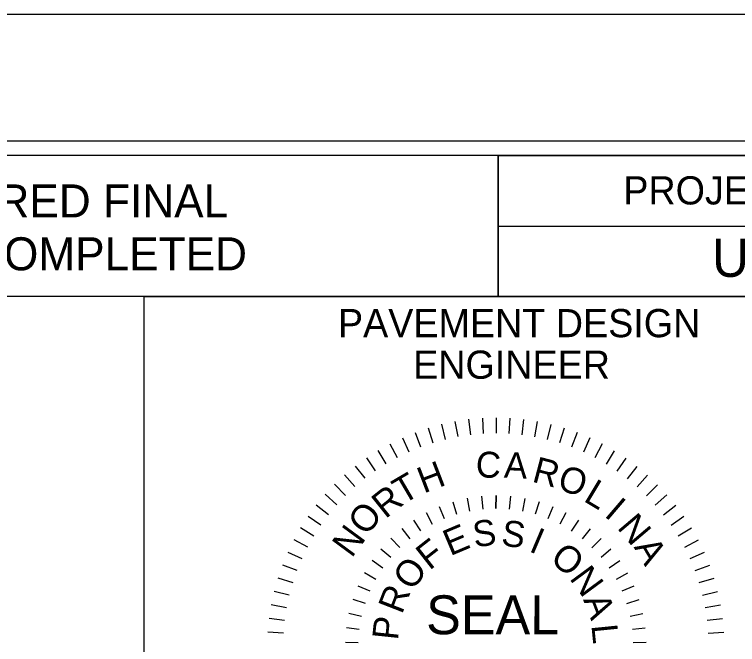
# Model space of a CAD drawing. Extents: x 2294370 to 2294957, y 719276 to 719941.
# Drawn here: x 2294731.39 to 2294757.04, y 719473.99 to 719496.34 of the extents above; entities that cross this region are included whole.
import ezdxf

# ---------------------------------------------------------------- set-up
doc = ezdxf.new("R2010")
doc.units = 0
for name, color, linetype in [('Default', 7, 'Continuous'), ('Sheet Cutting Line CELL', 7, 'Continuous'), ('Sheet Data Field CELL', 7, 'Continuous'), ('Sheet Plan CELL', 7, 'Continuous'), ('Sheet Plot Border Inside CELL', 7, 'Continuous'), ('Sheet Plot Border Outside CELL', 7, 'Continuous'), ('Sheet Sticker Exception Certification CELL', 7, 'Continuous'), ('Sheet Typical CELL', 7, 'Continuous')]:
    doc.layers.add(name, color=color, linetype=linetype)

msp = doc.modelspace()

# ---------------------------------------------------------------- linework, layer by layer
at = {"layer": 'Default'}
for p, q in [((2294747.502, 719481.976), (2294747.568, 719481.428)), ((2294747.99, 719482.019), (2294748.022, 719481.468)), ((2294748.479, 719482.033), (2294748.478, 719481.481)), ((2294748.968, 719482.018), (2294748.934, 719481.467)), ((2294749.455, 719481.973), (2294749.388, 719481.425)), ((2294746.541, 719481.801), (2294746.671, 719481.265)), ((2294747.019, 719481.903), (2294747.117, 719481.36)), ((2294749.939, 719481.899), (2294749.839, 719481.356)), ((2294750.417, 719481.796), (2294750.285, 719481.26)), ((2294745.606, 719481.512), (2294745.801, 719480.995)), ((2294746.068, 719481.671), (2294746.232, 719481.142)), ((2294750.889, 719481.664), (2294750.724, 719481.136)), ((2294751.35, 719481.504), (2294751.154, 719480.987)), ((2294745.154, 719481.324), (2294745.379, 719480.821)), ((2294751.802, 719481.315), (2294751.575, 719480.812)), ((2294744.713, 719481.111), (2294744.969, 719480.622)), ((2294752.242, 719481.101), (2294751.985, 719480.612)), ((2294744.286, 719480.871), (2294744.572, 719480.399)), ((2294752.668, 719480.859), (2294752.381, 719480.388)), ((2294743.875, 719480.606), (2294744.188, 719480.152)), ((2294753.078, 719480.593), (2294752.764, 719480.14)), ((2294743.481, 719480.317), (2294743.821, 719479.882)), ((2294753.472, 719480.303), (2294753.131, 719479.869)), ((2294743.105, 719480.004), (2294743.47, 719479.59)), ((2294753.848, 719479.989), (2294753.481, 719479.576)), ((2294742.748, 719479.669), (2294743.138, 719479.278)), ((2294754.203, 719479.653), (2294753.812, 719479.263)), ((2294742.412, 719479.314), (2294742.825, 719478.947)), ((2294747.449, 719479.174), (2294747.537, 719478.722)), ((2294747.959, 719479.248), (2294748.003, 719478.79)), ((2294748.475, 719479.272), (2294748.474, 719478.812)), ((2294748.474, 719478.812), (2294748.475, 719479.272)), ((2294748.991, 719479.246), (2294748.945, 719478.789)), ((2294749.5, 719479.171), (2294749.412, 719478.72)), ((2294754.538, 719479.296), (2294754.124, 719478.931)), ((2294742.098, 719478.938), (2294742.532, 719478.597)), ((2294746.948, 719479.052), (2294747.079, 719478.61)), ((2294750.001, 719479.047), (2294749.869, 719478.606)), ((2294754.851, 719478.92), (2294754.416, 719478.58)), ((2294745.993, 719478.664), (2294746.206, 719478.257)), ((2294746.461, 719478.881), (2294746.634, 719478.454)), ((2294750.488, 719478.876), (2294750.314, 719478.449)), ((2294750.955, 719478.657), (2294750.741, 719478.25)), ((2294741.808, 719478.544), (2294742.261, 719478.23)), ((2294745.548, 719478.403), (2294745.799, 719478.017)), ((2294751.4, 719478.395), (2294751.147, 719478.01)), ((2294755.14, 719478.526), (2294754.686, 719478.213)), ((2294741.542, 719478.134), (2294742.013, 719477.847)), ((2294755.405, 719478.115), (2294754.933, 719477.829)), ((2294745.13, 719478.101), (2294745.418, 719477.741)), ((2294751.817, 719478.091), (2294751.528, 719477.732)), ((2294741.3, 719477.708), (2294741.789, 719477.451)), ((2294744.744, 719477.759), (2294745.065, 719477.429)), ((2294752.202, 719477.748), (2294751.88, 719477.419)), ((2294755.645, 719477.688), (2294755.156, 719477.432)), ((2294744.392, 719477.382), (2294744.743, 719477.085)), ((2294752.553, 719477.37), (2294752.201, 719477.074)), ((2294741.086, 719477.268), (2294741.589, 719477.041)), ((2294755.858, 719477.247), (2294755.355, 719477.022)), ((2294744.078, 719476.973), (2294744.456, 719476.71)), ((2294752.866, 719476.96), (2294752.487, 719476.699)), ((2294740.897, 719476.817), (2294741.414, 719476.62)), ((2294756.046, 719476.795), (2294755.529, 719476.6)), ((2294740.737, 719476.355), (2294741.265, 719476.19)), ((2294743.806, 719476.535), (2294744.207, 719476.31)), ((2294753.137, 719476.522), (2294752.735, 719476.298)), ((2294756.205, 719476.333), (2294755.676, 719476.169)), ((2294743.576, 719476.072), (2294743.998, 719475.888)), ((2294740.605, 719475.883), (2294741.141, 719475.751)), ((2294753.365, 719476.058), (2294752.943, 719475.875)), ((2294756.335, 719475.86), (2294755.799, 719475.73)), ((2294743.393, 719475.59), (2294743.831, 719475.448)), ((2294753.547, 719475.576), (2294753.109, 719475.435)), ((2294740.502, 719475.405), (2294741.045, 719475.305)), ((2294756.437, 719475.382), (2294755.894, 719475.284)), ((2294743.256, 719475.093), (2294743.705, 719474.993)), ((2294753.682, 719475.078), (2294753.232, 719474.98)), ((2294740.428, 719474.921), (2294740.976, 719474.854)), ((2294756.51, 719474.899), (2294755.962, 719474.833)), ((2294743.169, 719474.584), (2294743.625, 719474.529)), ((2294753.768, 719474.569), (2294753.312, 719474.515)), ((2294740.383, 719474.434), (2294740.934, 719474.4)), ((2294756.553, 719474.411), (2294756.002, 719474.379)), ((2294743.13, 719474.07), (2294743.59, 719474.058)), ((2294753.805, 719474.055), (2294753.345, 719474.044))]:
    msp.add_line(p, q, dxfattribs=at)
at = {"layer": 'Sheet Cutting Line CELL'}
msp.add_line((2294791.96, 719496.338), (2294455.16, 719496.338), dxfattribs=at)
at = {"layer": 'Sheet Plan CELL'}
msp.add_lwpolyline([(2294762.275, 719463.828), (2294735.99, 719463.828), (2294735.99, 719486.328), (2294762.275, 719486.328)], dxfattribs=at)
at = {"layer": 'Sheet Plot Border Inside CELL'}
msp.add_lwpolyline([(2294791.06, 719491.848), (2294457.76, 719491.848), (2294457.76, 719280.828), (2294791.06, 719280.828)], close=True, dxfattribs=at)
at = {"layer": 'Sheet Plot Border Outside CELL'}
for points in [[(2294455.16, 719276.338), (2294791.96, 719276.338), (2294791.96, 719496.338), (2294455.16, 719496.338)], [(2294791.96, 719496.338), (2294455.16, 719496.338), (2294455.16, 719276.338), (2294791.96, 719276.338)]]:
    msp.add_lwpolyline(points, close=True, dxfattribs=at)
at = {"layer": 'Sheet Sticker Exception Certification CELL'}
for p, q in [((2294705.926, 719491.341), (2294748.55, 719491.341)), ((2294748.55, 719491.338), (2294748.55, 719486.331)), ((2294748.55, 719486.334), (2294705.926, 719486.334))]:
    msp.add_line(p, q, dxfattribs=at)
at = {"layer": 'Sheet Typical CELL'}
msp.add_line((2294748.55, 719488.828), (2294788.56, 719488.828), dxfattribs=at)
for points in [[(2294788.56, 719491.338), (2294488.56, 719491.338), (2294488.56, 719281.338), (2294788.56, 719281.338)], [(2294748.55, 719491.338), (2294788.56, 719491.338), (2294788.56, 719486.328), (2294748.55, 719486.328)]]:
    msp.add_lwpolyline(points, close=True, dxfattribs=at)

# ---------------------------------------------------------------- texts
at = {"layer": 'Default'}
for s, height, rotation, p in [('C', 0.92, 357.2756, (2294747.74, 719479.927)), ('A', 0.92, 357.2756, (2294748.745, 719479.907)), ('H', 0.928, 20.9863, (2294745.91, 719479.338)), ('R', 0.924, 345.2663, (2294749.719, 719479.77)), ('O', 0.926, 342.2095, (2294750.61, 719479.504)), ('T', 0.934, 30.4182, (2294745.169, 719478.939)), ('L', 0.935, 329.0732, (2294751.544, 719479.093)), ('R', 0.939, 38.5792, (2294744.55, 719478.425)), ('I', 0.939, 319.4977, (2294752.285, 719478.558)), ('O', 0.94, 51.6359, (2294743.883, 719477.807)), ('N', 0.94, 310.2033, (2294752.745, 719478.124)), ('S', 0.921, 7.5668, (2294747.714, 719477.431)), ('S', 0.921, 352.2705, (2294748.632, 719477.506)), ('N', 0.939, 53.5954, (2294743.354, 719477.031)), ('E', 0.929, 22.863, (2294746.85, 719477.116)), ('I', 0.929, 336.9743, (2294749.61, 719477.306)), ('F', 0.938, 38.1593, (2294746.113, 719476.597)), ('A', 0.937, 300.4357, (2294753.351, 719477.444)), ('O', 0.939, 321.678, (2294750.35, 719476.947)), ('O', 0.939, 53.4555, (2294745.501, 719475.856)), ('N', 0.939, 306.3818, (2294751.058, 719476.33)), ('R', 0.93, 68.7517, (2294745.136, 719475.031)), ('SEAL', 1.3802, 359.9186, (2294745.995, 719474.351)), ('A', 0.93, 291.0855, (2294751.561, 719475.576)), ('P', 0.92, 84.048, (2294744.995, 719474.12)), ('L', 0.92, 275.7893, (2294751.857, 719474.666))]:
    msp.add_text(s, height=height, rotation=rotation, dxfattribs=at).set_placement(p)
at = {"layer": 'Sheet Data Field CELL'}
msp.add_text('U-4700CA', height=1.35, rotation=360, dxfattribs=at).set_placement((2294756.142, 719487.029))
at = {"layer": 'Sheet Plan CELL'}
for s, height, p in [('PAVEMENT DESIGN', 1.00002, (2294742.868, 719484.888)), ('ENGINEER', 1, (2294745.534, 719483.414))]:
    msp.add_text(s, height=height, dxfattribs=at).set_placement(p)
at = {"layer": 'Sheet Sticker Exception Certification CELL'}
for s, p in [('DOCUMENT NOT CONSIDERED FINAL', (2294710.416, 719489.137)), ('UNLESS ALL SIGNATURES COMPLETED', (2294709.335, 719487.261))]:
    msp.add_text(s, height=1.17193, dxfattribs=at).set_placement(p)
at = {"layer": 'Sheet Typical CELL'}
msp.add_text('PROJECT REFERENCE NO.', height=1.00002, dxfattribs=at).set_placement((2294752.99, 719489.598))

doc.saveas('drawing.dxf')
